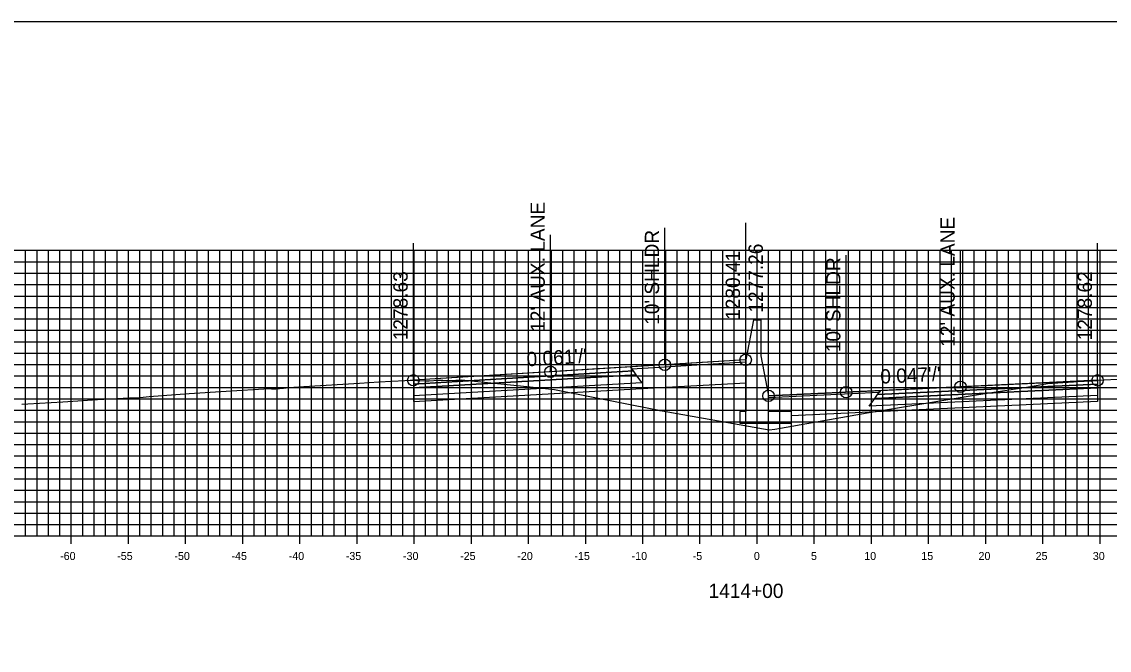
# Model space of a CAD drawing. Extents: x 674939 to 678919, y 750652 to 765176.
# Drawn here: x 678674.2 to 678769.3, y 757297.6 to 757352.6 of the extents above; entities that cross this region are included whole.
import ezdxf

# ---------------------------------------------------------------- set-up
doc = ezdxf.new("R2010")
doc.units = 0
for name, color, linetype in [('Level 10', 7, 'Continuous'), ('Level 17', 7, 'Continuous'), ('Level 18', 7, 'Continuous'), ('Level 19', 7, 'Continuous'), ('Level 20', 7, 'Continuous'), ('Level 22', 7, 'Continuous'), ('Level 23', 7, 'Continuous'), ('Level 4', 7, 'Continuous'), ('Level 8', 7, 'Continuous'), ('Level 9', 7, 'Continuous')]:
    doc.layers.add(name, color=color, linetype=linetype)

msp = doc.modelspace()

# ---------------------------------------------------------------- linework, layer by layer
at = {"layer": 'Level 10'}
msp.add_lwpolyline([(678674.194, 757319.078), (678674.726, 757319.116), (678677.78, 757319.303), (678680.821, 757319.484), (678683.634, 757319.65), (678683.92, 757319.65), (678684.562, 757319.669), (678685.347, 757319.743), (678688.833, 757320.007), (678692.068, 757320.22), (678695.835, 757320.45), (678696.044, 757320.441), (678696.435, 757320.429), (678697.089, 757320.499), (678697.574, 757320.548), (678698.882, 757320.631), (678703.748, 757320.93), (678705.446, 757321.034), (678707.698, 757321.149), (678708.169, 757321.173), (678708.304, 757321.182), (678708.419, 757321.178), (678708.457, 757321.177), (678708.754, 757321.168), (678709.57, 757321.138), (678709.838, 757321.141), (678710.637, 757321.175), (678710.837, 757321.185), (678711.037, 757321.177), (678711.97, 757321.171), (678712.17, 757321.176), (678712.392, 757321.177), (678712.659, 757321.208), (678718.686, 757320.592), (678720.805, 757320.374), (678729.786, 757318.59), (678730.001, 757318.546), (678730.222, 757318.505), (678739.598, 757316.827), (678740.094, 757316.912), (678748.174, 757318.318), (678749.925, 757318.616), (678757.333, 757319.831), (678762.278, 757320.598), (678764.112, 757320.934), (678764.129, 757320.933), (678764.142, 757320.935), (678764.191, 757320.93), (678764.239, 757320.913), (678764.385, 757320.919), (678766.202, 757321.037), (678766.543, 757321.06), (678767.753, 757321.129), (678768.142, 757321.155), (678768.262, 757321.162), (678768.322, 757321.172), (678770.624, 757321.31)], dxfattribs=at)
at = {"layer": 'Level 17'}
for points in [[(678738.203, 757326.464), (678737.533, 757322.964)], [(678738.203, 757326.464), (678738.203, 757326.464)], [(678738.203, 757326.464), (678738.863, 757326.464)], [(678738.863, 757326.464), (678738.863, 757323.31)], [(678738.863, 757323.31), (678739.533, 757319.81)], [(678737.533, 757322.964), (678737.533, 757318.435), (678737.033, 757318.435), (678737.033, 757317.435), (678741.533, 757317.435), (678741.533, 757318.435), (678739.533, 757318.435), (678739.533, 757319.81)]]:
    msp.add_lwpolyline(points, dxfattribs=at)
at = {"layer": 'Level 18'}
for points in [[(678737.533, 757322.964), (678730.457, 757322.529), (678720.457, 757321.914), (678708.457, 757321.177)], [(678768.322, 757321.172), (678756.322, 757320.604), (678746.322, 757320.131), (678739.533, 757319.81)]]:
    msp.add_lwpolyline(points, dxfattribs=at)
for points in [[(678708.457, 757321.177), (678708.457, 757320.847), (678727.707, 757322.005), (678727.457, 757322.345)], [(678727.575, 757322.184), (678737.533, 757322.804), (678737.533, 757322.964), (678727.457, 757322.345)], [(678768.322, 757321.172), (678768.322, 757320.842), (678749.072, 757319.933), (678749.322, 757320.273)], [(678749.204, 757320.113), (678739.533, 757319.65), (678739.533, 757319.81), (678749.322, 757320.273)]]:
    msp.add_lwpolyline(points, close=True, dxfattribs=at)
at = {"layer": 'Level 19'}
for points in [[(678708.457, 757320.847), (678708.457, 757320.517), (678727.957, 757321.665), (678727.707, 757322.005)], [(678708.457, 757320.517), (678708.457, 757319.857), (678728.457, 757320.985), (678727.957, 757321.665)], [(678768.322, 757320.512), (678768.322, 757319.852), (678748.322, 757318.913), (678748.822, 757319.593)], [(678768.322, 757320.842), (678768.322, 757320.512), (678748.822, 757319.593), (678749.072, 757319.933)]]:
    msp.add_lwpolyline(points, close=True, dxfattribs=at)
for points in [[(678708.457, 757319.857), (678708.457, 757319.317), (678728.457, 757320.445)], [(678728.457, 757320.445), (678737.533, 757320.957)], [(678768.322, 757319.852), (678768.323, 757319.312), (678748.322, 757318.373)], [(678748.322, 757318.373), (678741.533, 757318.054)]]:
    msp.add_lwpolyline(points, dxfattribs=at)
at = {"layer": 'Level 20'}
for p, q in [((678638.533, 757332.551), (678838.533, 757332.551)), ((678674.533, 757307.551), (678674.533, 757332.551)), ((678675.533, 757307.551), (678675.533, 757332.551)), ((678676.533, 757307.551), (678676.533, 757332.551)), ((678677.533, 757307.551), (678677.533, 757332.551)), ((678678.533, 757307.551), (678678.533, 757332.551)), ((678679.533, 757307.551), (678679.533, 757332.551)), ((678680.533, 757307.551), (678680.533, 757332.551)), ((678681.533, 757307.551), (678681.533, 757332.551)), ((678682.533, 757307.551), (678682.533, 757332.551)), ((678683.533, 757307.551), (678683.533, 757332.551)), ((678684.533, 757307.551), (678684.533, 757332.551)), ((678685.533, 757307.551), (678685.533, 757332.551)), ((678686.533, 757307.551), (678686.533, 757332.551)), ((678687.533, 757307.551), (678687.533, 757332.551)), ((678688.533, 757307.551), (678688.533, 757332.551)), ((678689.533, 757307.551), (678689.533, 757332.551)), ((678690.533, 757307.551), (678690.533, 757332.551)), ((678691.533, 757307.551), (678691.533, 757332.551)), ((678692.533, 757307.551), (678692.533, 757332.551)), ((678693.533, 757307.551), (678693.533, 757332.551)), ((678694.533, 757307.551), (678694.533, 757332.551)), ((678695.533, 757307.551), (678695.533, 757332.551)), ((678696.533, 757307.551), (678696.533, 757332.551)), ((678697.533, 757307.551), (678697.533, 757332.551)), ((678698.533, 757307.551), (678698.533, 757332.551)), ((678699.533, 757307.551), (678699.533, 757332.551)), ((678700.533, 757307.551), (678700.533, 757332.551)), ((678701.533, 757307.551), (678701.533, 757332.551)), ((678702.533, 757307.551), (678702.533, 757332.551)), ((678703.533, 757307.551), (678703.533, 757332.551)), ((678704.533, 757307.551), (678704.533, 757332.551)), ((678705.533, 757307.551), (678705.533, 757332.551)), ((678706.533, 757307.551), (678706.533, 757332.551)), ((678707.533, 757307.551), (678707.533, 757332.551)), ((678708.533, 757307.551), (678708.533, 757332.551)), ((678709.533, 757307.551), (678709.533, 757332.551)), ((678710.533, 757307.551), (678710.533, 757332.551)), ((678711.533, 757307.551), (678711.533, 757332.551)), ((678712.533, 757307.551), (678712.533, 757332.551)), ((678713.533, 757307.551), (678713.533, 757332.551)), ((678714.533, 757307.551), (678714.533, 757332.551)), ((678715.533, 757307.551), (678715.533, 757332.551)), ((678716.533, 757307.551), (678716.533, 757332.551)), ((678717.533, 757307.551), (678717.533, 757332.551)), ((678718.533, 757307.551), (678718.533, 757332.551)), ((678719.533, 757307.551), (678719.533, 757332.551)), ((678720.533, 757307.551), (678720.533, 757332.551)), ((678721.533, 757307.551), (678721.533, 757332.551)), ((678722.533, 757307.551), (678722.533, 757332.551)), ((678723.533, 757307.551), (678723.533, 757332.551)), ((678724.533, 757307.551), (678724.533, 757332.551)), ((678725.533, 757307.551), (678725.533, 757332.551)), ((678726.533, 757307.551), (678726.533, 757332.551)), ((678727.533, 757307.551), (678727.533, 757332.551)), ((678728.533, 757307.551), (678728.533, 757332.551)), ((678729.533, 757307.551), (678729.533, 757332.551)), ((678730.533, 757307.551), (678730.533, 757332.551)), ((678731.533, 757307.551), (678731.533, 757332.551)), ((678732.533, 757307.551), (678732.533, 757332.551)), ((678733.533, 757307.551), (678733.533, 757332.551)), ((678734.533, 757307.551), (678734.533, 757332.551)), ((678735.533, 757307.551), (678735.533, 757332.551)), ((678736.533, 757307.551), (678736.533, 757332.551)), ((678737.533, 757307.551), (678737.533, 757332.551)), ((678738.533, 757307.551), (678738.533, 757332.551)), ((678739.533, 757307.551), (678739.533, 757332.551)), ((678740.533, 757307.551), (678740.533, 757332.551)), ((678741.533, 757307.551), (678741.533, 757332.551)), ((678742.533, 757307.551), (678742.533, 757332.551)), ((678743.533, 757307.551), (678743.533, 757332.551)), ((678744.533, 757307.551), (678744.533, 757332.551)), ((678745.533, 757307.551), (678745.533, 757332.551)), ((678746.533, 757307.551), (678746.533, 757332.551)), ((678747.533, 757307.551), (678747.533, 757332.551)), ((678748.533, 757307.551), (678748.533, 757332.551)), ((678749.533, 757307.551), (678749.533, 757332.551)), ((678750.533, 757307.551), (678750.533, 757332.551)), ((678751.533, 757307.551), (678751.533, 757332.551)), ((678752.533, 757307.551), (678752.533, 757332.551)), ((678753.533, 757307.551), (678753.533, 757332.551)), ((678754.533, 757307.551), (678754.533, 757332.551)), ((678755.533, 757307.551), (678755.533, 757332.551)), ((678756.533, 757307.551), (678756.533, 757332.551)), ((678757.533, 757307.551), (678757.533, 757332.551)), ((678758.533, 757307.551), (678758.533, 757332.551)), ((678759.533, 757307.551), (678759.533, 757332.551)), ((678760.533, 757307.551), (678760.533, 757332.551)), ((678761.533, 757307.551), (678761.533, 757332.551)), ((678762.533, 757307.551), (678762.533, 757332.551)), ((678763.533, 757307.551), (678763.533, 757332.551)), ((678764.533, 757307.551), (678764.533, 757332.551)), ((678765.533, 757307.551), (678765.533, 757332.551)), ((678766.533, 757307.551), (678766.533, 757332.551)), ((678767.533, 757307.551), (678767.533, 757332.551)), ((678768.533, 757307.551), (678768.533, 757332.551)), ((678638.533, 757331.551), (678838.533, 757331.551)), ((678638.533, 757330.551), (678838.533, 757330.551)), ((678638.533, 757329.551), (678838.533, 757329.551)), ((678638.533, 757328.551), (678838.533, 757328.551)), ((678638.533, 757327.551), (678838.533, 757327.551)), ((678638.533, 757326.551), (678838.533, 757326.551)), ((678638.533, 757325.551), (678838.533, 757325.551)), ((678638.533, 757324.551), (678838.533, 757324.551)), ((678638.533, 757323.551), (678838.533, 757323.551)), ((678638.533, 757322.551), (678838.533, 757322.551)), ((678638.533, 757321.551), (678838.533, 757321.551)), ((678638.533, 757320.551), (678838.533, 757320.551)), ((678638.533, 757319.551), (678838.533, 757319.551)), ((678638.533, 757318.551), (678838.533, 757318.551)), ((678638.533, 757317.551), (678838.533, 757317.551)), ((678638.533, 757316.551), (678838.533, 757316.551)), ((678638.533, 757315.551), (678838.533, 757315.551)), ((678638.533, 757314.551), (678838.533, 757314.551)), ((678638.533, 757313.551), (678838.533, 757313.551)), ((678638.533, 757312.551), (678838.533, 757312.551)), ((678638.533, 757311.551), (678838.533, 757311.551)), ((678638.533, 757310.551), (678838.533, 757310.551)), ((678638.533, 757309.551), (678838.533, 757309.551)), ((678638.533, 757308.551), (678838.533, 757308.551)), ((678638.533, 757307.551), (678838.533, 757307.551))]:
    msp.add_line(p, q, dxfattribs=at)
at = {"layer": 'Level 23'}
for p, q in [((678730.457, 757322.529), (678730.457, 757334.529)), ((678737.533, 757322.964), (678737.533, 757334.964)), ((678720.457, 757321.914), (678720.457, 757333.914)), ((678708.457, 757321.177), (678708.457, 757333.177)), ((678756.322, 757320.604), (678756.322, 757332.604)), ((678768.322, 757321.172), (678768.322, 757333.172)), ((678739.533, 757319.81), (678739.533, 757331.81)), ((678746.322, 757320.131), (678746.322, 757332.131))]:
    msp.add_line(p, q, dxfattribs=at)
at = {"layer": 'Level 4'}
msp.add_lwpolyline([(678578.533, 757132.551), (678918.533, 757132.551), (678918.533, 757352.551), (678578.533, 757352.551)], close=True, dxfattribs=at)
for centre in [(678737.533, 757322.964), (678720.457, 757321.914), (678730.457, 757322.529), (678708.457, 757321.177), (678768.322, 757321.172), (678739.533, 757319.81), (678746.322, 757320.131), (678756.322, 757320.604)]:
    msp.add_circle(centre, 0.5, dxfattribs=at)
at = {"layer": 'Level 8'}
for p, q in [((678678.533, 757306.851), (678678.533, 757308.251)), ((678683.533, 757306.851), (678683.533, 757308.251)), ((678688.533, 757306.851), (678688.533, 757308.251)), ((678693.533, 757306.851), (678693.533, 757308.251)), ((678698.533, 757306.851), (678698.533, 757308.251)), ((678703.533, 757306.851), (678703.533, 757308.251)), ((678708.533, 757306.851), (678708.533, 757308.251)), ((678713.533, 757306.851), (678713.533, 757308.251)), ((678718.533, 757306.851), (678718.533, 757308.251)), ((678723.533, 757306.851), (678723.533, 757308.251)), ((678728.533, 757306.851), (678728.533, 757308.251)), ((678733.533, 757306.851), (678733.533, 757308.251)), ((678738.533, 757306.851), (678738.533, 757308.251)), ((678743.533, 757306.851), (678743.533, 757308.251)), ((678748.533, 757306.851), (678748.533, 757308.251)), ((678753.533, 757306.851), (678753.533, 757308.251)), ((678758.533, 757306.851), (678758.533, 757308.251)), ((678763.533, 757306.851), (678763.533, 757308.251)), ((678768.533, 757306.851), (678768.533, 757308.251)), ((678638.533, 757307.551), (678838.533, 757307.551))]:
    msp.add_line(p, q, dxfattribs=at)

# ---------------------------------------------------------------- texts
at = {"layer": 'Level 22'}
for s, rotation, p in [("0.061'/'", 3.51801, (678718.404, 757322.389)), ("0.047'/'", 2.70862, (678749.341, 757320.875))]:
    msp.add_text(s, height=1.25, rotation=rotation, dxfattribs=at).set_placement(p)
at = {"layer": 'Level 23'}
for s, p in [("12' AUX. LANE", (678719.957, 757325.414)), ("12' AUX. LANE", (678755.822, 757324.104)), ("10' SHLDR", (678729.957, 757326.029)), ('1277.26', (678739.033, 757327.094)), ('1280.41', (678737.033, 757326.464)), ("10' SHLDR", (678745.822, 757323.631)), ('1278.63', (678707.957, 757324.677)), ('1278.62', (678767.822, 757324.672))]:
    msp.add_text(s, height=1.25, rotation=90, dxfattribs=at).set_placement(p)
at = {"layer": 'Level 9'}
for s, height, p in [('-60', 0.7, (678677.552, 757305.451)), ('-55', 0.7, (678682.546, 757305.451)), ('-50', 0.7, (678687.552, 757305.451)), ('-45', 0.7, (678692.546, 757305.451)), ('-40', 0.7, (678697.552, 757305.451)), ('-35', 0.7, (678702.546, 757305.451)), ('-30', 0.7, (678707.552, 757305.451)), ('-25', 0.7, (678712.546, 757305.451)), ('-20', 0.7, (678717.552, 757305.451)), ('-15', 0.7, (678722.546, 757305.451)), ('-10', 0.7, (678727.552, 757305.451)), ('-5', 0.7, (678732.896, 757305.451)), ('0', 0.7, (678738.252, 757305.451)), ('5', 0.7, (678743.246, 757305.451)), ('10', 0.7, (678747.902, 757305.451)), ('15', 0.7, (678752.896, 757305.451)), ('20', 0.7, (678757.902, 757305.451)), ('25', 0.7, (678762.896, 757305.451)), ('30', 0.7, (678767.902, 757305.451)), ('1414+00', 1.25, (678734.281, 757302.126))]:
    msp.add_text(s, height=height, dxfattribs=at).set_placement(p)

doc.saveas('drawing.dxf')
